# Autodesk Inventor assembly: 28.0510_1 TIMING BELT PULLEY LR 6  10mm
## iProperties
Created: 2007-06
Part Number: 28.0510_1 TIMING BELT PULLEY LR 6  10mm
Document SubType Name: Assembly
Designer: Andy Moles
Author: Andy Moles
